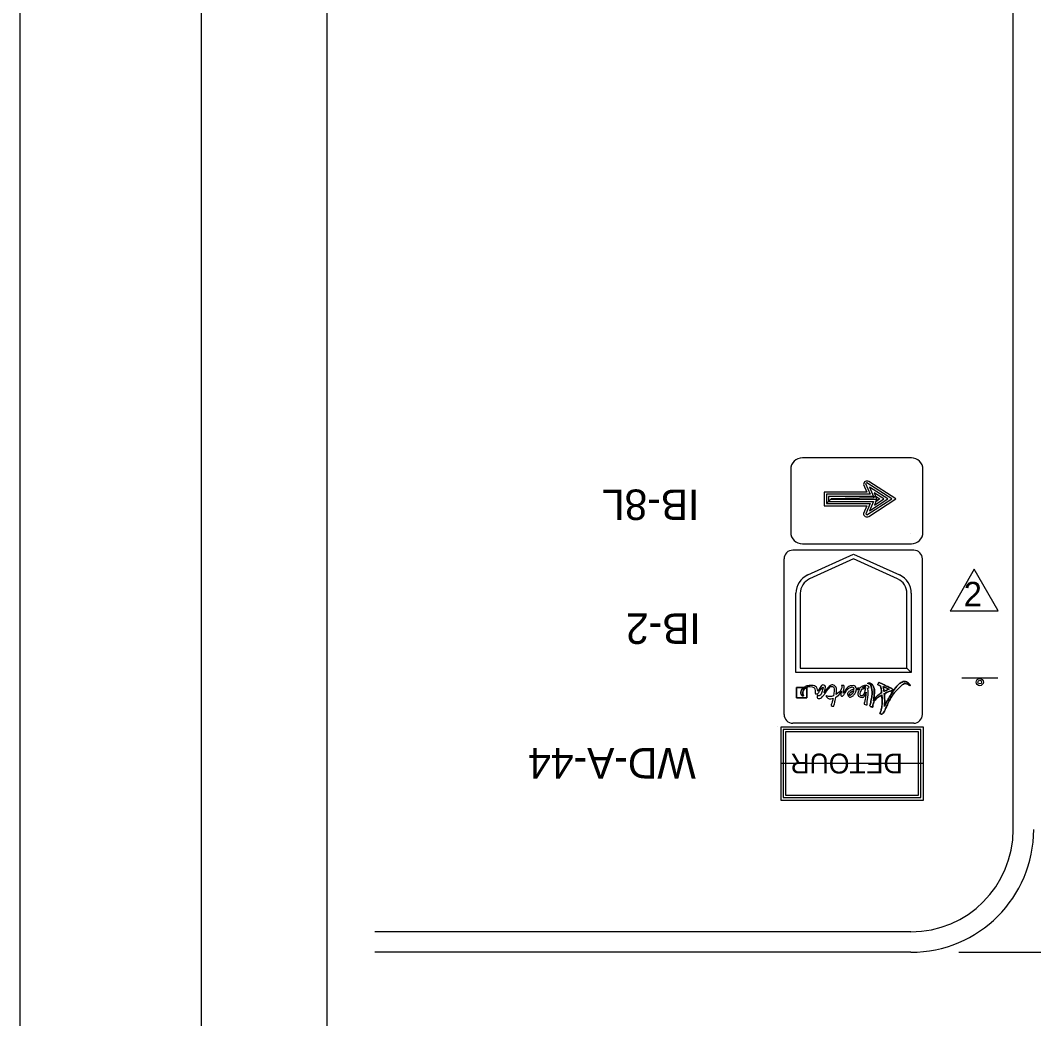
# Model space of a CAD drawing. Extents: x 1482 to 1692, y 225 to 494.
# Drawn here: x 1482.4 to 1542.3, y 383.2 to 442.2 of the extents above; entities that cross this region are included whole.
import ezdxf

# ---------------------------------------------------------------- set-up
doc = ezdxf.new("R2010")
doc.units = 0
for name, color, linetype in [('Level 17', 7, 'Continuous'), ('Level 2', 7, 'Continuous'), ('Level 53', 7, 'Continuous'), ('Level 60', 7, 'Continuous')]:
    doc.layers.add(name, color=color, linetype=linetype)

msp = doc.modelspace()

# ---------------------------------------------------------------- linework, layer by layer
at = {"layer": 'Level 17'}
for p, q in [((1535.059, 416.333), (1528.622, 416.333)), ((1527.938, 415.636), (1527.938, 411.938)), ((1535.737, 411.938), (1535.737, 415.636)), ((1532.238, 414.761), (1532.43, 414.3)), ((1534.152, 413.897), (1532.539, 414.928)), ((1532.43, 414.3), (1529.914, 414.3)), ((1529.914, 414.3), (1529.914, 413.501)), ((1532.539, 412.872), (1534.152, 413.897)), ((1529.914, 413.501), (1532.424, 413.501)), ((1532.43, 413.501), (1532.232, 413.039)), ((1535.002, 411.83), (1535.002, 411.83)), ((1528.622, 411.252), (1535.059, 411.252)), ((1540.173, 403.317), (1538.039, 403.317)), ((1527.164, 400.431), (1527.164, 400.431)), ((1527.164, 400.431), (1527.164, 400.431)), ((1527.164, 400.431), (1527.164, 400.431)), ((1527.164, 400.431), (1527.164, 400.431)), ((1535.773, 398.266), (1527.336, 398.266))]:
    msp.add_line(p, q, dxfattribs=at)
for points in [[(1529.814, 416.339), (1529.922, 416.339)], [(1530.049, 413.622), (1532.622, 413.622), (1532.366, 413.027), (1532.436, 412.962), (1533.914, 413.897), (1532.43, 414.845), (1532.359, 414.806), (1532.622, 414.173), (1530.043, 414.173), (1530.049, 413.622), (1530.17, 413.756), (1532.814, 413.756), (1532.59, 413.206), (1533.672, 413.897), (1532.59, 414.588), (1532.814, 414.038), (1530.17, 414.038), (1530.17, 413.756), (1530.306, 413.885), (1533.025, 413.885), (1532.878, 413.538), (1533.434, 413.897), (1532.864, 414.262), (1532.948, 414.058), (1533.204, 413.897), (1532.96, 413.736), (1533.012, 413.903), (1532.948, 414.058), (1532.82, 413.968), (1530.312, 413.903), (1530.306, 413.885)], [(1530.049, 413.622), (1532.622, 413.622)]]:
    msp.add_lwpolyline(points, dxfattribs=at)
for points in [[(1527.342, 396.112), (1535.768, 396.112), (1535.768, 400.42), (1527.342, 400.42)], [(1527.482, 396.254), (1535.628, 396.254), (1535.628, 400.28), (1527.482, 400.28)], [(1527.624, 396.394), (1535.486, 396.394), (1535.486, 400.14), (1527.624, 400.14)]]:
    msp.add_lwpolyline(points, close=True, dxfattribs=at)
for radius in [0.213, 0.107]:
    msp.add_circle((1539.102, 403.078), radius, dxfattribs=at)
for centre, radius, start, end in [((1528.623, 415.641), 0.692, 90, 180), ((1535.053, 415.641), 0.692, 0, 90), ((1532.435, 414.761), 0.199, 57.50145, 179.89494), ((1532.432, 413.038), 0.199, 179.89425, 302.49622), ((1528.623, 411.937), 0.692, 180, 270), ((1535.053, 411.937), 0.692, 270, 0)]:
    msp.add_arc(centre, radius, start, end, dxfattribs=at)
at = {"layer": 'Level 2'}
for p, q in [((1541.08, 394.372), (1541.08, 469.813)), ((1535.197, 410.874), (1528.055, 410.874)), ((1527.537, 401.169), (1527.537, 410.356)), ((1528.938, 409.409), (1531.647, 410.641)), ((1531.647, 410.36), (1529.044, 409.176)), ((1531.647, 410.641), (1534.356, 409.409)), ((1534.25, 409.176), (1531.647, 410.36)), ((1535.715, 401.169), (1535.715, 410.356)), ((1528.239, 403.655), (1528.239, 408.323)), ((1528.495, 408.323), (1528.495, 403.91)), ((1534.799, 403.91), (1534.799, 408.323)), ((1535.055, 408.323), (1535.055, 403.655)), ((1535.055, 403.655), (1528.239, 403.655)), ((1528.495, 403.91), (1534.799, 403.91)), ((1535.055, 403.655), (1534.799, 403.91)), ((1534.799, 403.91), (1535.055, 403.655)), ((1535.197, 400.651), (1528.055, 400.651)), ((1535.197, 400.651), (1528.055, 400.651)), ((1535.032, 388.323), (1503.354, 388.323)), ((1535.032, 387.114), (1503.354, 387.114)), ((1537.868, 387.114), (1555.432, 387.114))]:
    msp.add_line(p, q, dxfattribs=at)
for centre, radius, start, end in [((1528.055, 410.356), 0.518, 90, 180), ((1535.197, 410.356), 0.518, 360, 90), ((1529.432, 408.323), 1.193, 114.45682, 180), ((1529.432, 408.323), 0.937, 114.45682, 180), ((1533.862, 408.323), 0.937, 360, 65.54318), ((1533.862, 408.323), 1.193, 360, 65.54318), ((1528.055, 401.169), 0.518, 180, 270), ((1535.197, 401.169), 0.518, 270, 360), ((1535.032, 394.372), 6.048, 270, 359.99999), ((1535.032, 394.372), 7.258, 270, 359.99999)]:
    msp.add_arc(centre, radius, start, end, dxfattribs=at)
at = {"layer": 'Level 53'}
msp.add_line((1528.717, 402.766), (1528.867, 402.766), dxfattribs=at)
msp.add_lwpolyline([(1528.717, 402.766), (1528.276, 402.766), (1528.276, 402.158), (1528.885, 402.158), (1528.885, 402.766), (1528.867, 402.766)], dxfattribs=at)
for points, degree in [([(1532.53, 402.987), (1532.595, 402.977), (1532.681, 402.888), (1532.706, 402.742), (1532.753, 402.478), (1532.726, 402.218), (1532.648, 401.831), (1532.633, 401.757), (1532.583, 401.63), (1532.743, 401.606), (1532.793, 401.598), (1532.767, 401.623), (1532.781, 401.69), (1532.842, 401.979), (1533.078, 402.187), (1533.315, 402.326), (1533.34, 401.996), (1533.33, 401.629), (1533.268, 401.404), (1533.215, 401.214), (1533.153, 401.249), (1533.23, 401.209), (1533.312, 401.167), (1533.399, 401.223), (1533.47, 401.364), (1533.541, 401.505), (1533.867, 402.273), (1534.388, 402.791), (1534.655, 403.056), (1534.896, 402.92), (1534.944, 402.879), (1534.983, 402.846), (1534.998, 402.897), (1534.949, 402.949), (1534.733, 403.182), (1534.418, 403.049), (1534.304, 402.934), (1533.987, 402.617), (1533.618, 401.935), (1533.469, 401.645), (1533.483, 401.808), (1533.487, 402.082), (1533.457, 402.402), (1533.618, 402.481), (1533.763, 402.527), (1533.831, 402.545), (1533.905, 402.564), (1533.951, 402.594), (1533.952, 402.629), (1533.954, 402.666), (1533.904, 402.698), (1533.832, 402.732), (1533.705, 402.792), (1533.331, 402.969), (1533.239, 403.023), (1533.16, 403.068), (1533.121, 403.033), (1533.098, 402.983), (1533.067, 402.919), (1533.151, 402.882), (1533.232, 402.857), (1533.263, 402.749), (1533.288, 402.603), (1533.305, 402.442), (1533.115, 402.325), (1532.927, 402.169), (1532.82, 401.975), (1532.847, 402.137), (1532.916, 402.691), (1532.742, 402.925), (1532.703, 402.976), (1532.618, 403.033), (1532.535, 403.024), (1532.496, 403.021), (1532.476, 402.995), (1532.48, 402.987), (1532.484, 402.979), (1532.507, 402.99), (1532.53, 402.987)], 3), ([(1532.82, 401.975), (1532.847, 402.137), (1532.916, 402.691), (1532.742, 402.925), (1532.703, 402.976), (1532.618, 403.033), (1532.535, 403.024), (1532.496, 403.021), (1532.476, 402.995), (1532.48, 402.987), (1532.484, 402.979), (1532.507, 402.99), (1532.53, 402.987)], 3), ([(1533.457, 402.402), (1533.618, 402.481), (1533.763, 402.527), (1533.831, 402.545), (1533.905, 402.564), (1533.951, 402.594), (1533.952, 402.629), (1533.954, 402.666), (1533.904, 402.698), (1533.832, 402.732), (1533.705, 402.792), (1533.331, 402.969), (1533.239, 403.023), (1533.16, 403.068), (1533.121, 403.033), (1533.098, 402.983), (1533.067, 402.919), (1533.151, 402.882), (1533.232, 402.857)], 3), ([(1533.315, 402.326), (1533.34, 401.996), (1533.33, 401.629), (1533.268, 401.404), (1533.215, 401.214), (1533.153, 401.249), (1533.23, 401.209), (1533.312, 401.167), (1533.399, 401.223), (1533.47, 401.364), (1533.541, 401.505), (1533.867, 402.273), (1534.388, 402.791), (1534.655, 403.056), (1534.896, 402.92), (1534.944, 402.879), (1534.983, 402.846), (1534.998, 402.897), (1534.949, 402.949), (1534.733, 403.182), (1534.418, 403.049), (1534.304, 402.934), (1533.987, 402.617), (1533.618, 401.935), (1533.469, 401.645)], 3), ([(1528.885, 402.158), (1528.885, 402.158), (1528.885, 402.766), (1528.885, 402.766), (1528.885, 402.766), (1528.867, 402.766), (1528.867, 402.766), (1528.735, 402.687), (1528.646, 402.536), (1528.646, 402.412), (1528.647, 402.304), (1528.703, 402.31), (1528.697, 402.295), (1528.679, 402.252), (1528.544, 402.276), (1528.536, 402.428), (1528.53, 402.556), (1528.597, 402.681), (1528.717, 402.766), (1528.717, 402.766), (1528.276, 402.766), (1528.276, 402.766), (1528.276, 402.766), (1528.276, 402.158), (1528.276, 402.158), (1528.276, 402.158), (1528.885, 402.158), (1528.885, 402.158)], 3), ([(1528.867, 402.766), (1528.735, 402.687), (1528.646, 402.536), (1528.646, 402.412), (1528.647, 402.304), (1528.703, 402.31), (1528.697, 402.295), (1528.679, 402.252), (1528.544, 402.276), (1528.536, 402.428), (1528.53, 402.556), (1528.597, 402.681), (1528.717, 402.766)], 3), ([(1529.528, 402.535), (1529.513, 402.66), (1529.43, 402.876), (1529.093, 402.876), (1528.941, 402.876), (1528.812, 402.834), (1528.717, 402.766)], 3), ([(1528.867, 402.766), (1528.923, 402.799), (1528.987, 402.82), (1529.055, 402.82)], 2), ([(1529.055, 402.82), (1529.304, 402.82), (1529.369, 402.626), (1529.381, 402.53), (1529.389, 402.466), (1529.375, 402.374), (1529.485, 402.386), (1529.563, 402.395), (1529.632, 402.545), (1529.73, 402.672), (1529.814, 402.78), (1529.852, 402.77), (1529.832, 402.677), (1529.808, 402.56), (1529.71, 402.286), (1529.599, 402.266), (1529.547, 402.257), (1529.529, 402.347), (1529.505, 402.29), (1529.481, 402.234), (1529.503, 402.111), (1529.619, 402.111), (1529.699, 402.111), (1529.796, 402.197), (1529.876, 402.294), (1529.945, 402.379), (1530.296, 402.895), (1530.443, 402.784), (1530.511, 402.732), (1530.506, 402.52), (1530.462, 402.27)], 3), ([(1529.896, 402.462), (1529.974, 402.638), (1530.019, 402.863), (1529.901, 402.898), (1529.764, 402.938), (1529.655, 402.71), (1529.528, 402.535)], 3), ([(1530.614, 402.348), (1530.642, 402.583), (1530.632, 402.794), (1530.525, 402.861), (1530.328, 402.984), (1530.05, 402.66), (1529.896, 402.462)], 3), ([(1530.59, 402.184), (1530.72, 402.258), (1530.84, 402.382), (1530.928, 402.546)], 2), ([(1531.04, 402.426), (1531.054, 402.572), (1531.15, 402.892), (1530.987, 402.875), (1530.923, 402.869), (1530.951, 402.859), (1530.947, 402.804), (1530.933, 402.611), (1530.773, 402.448), (1530.614, 402.348)], 3), ([(1530.928, 402.546), (1530.913, 402.47), (1530.889, 402.387), (1530.887, 402.331), (1530.886, 402.271), (1530.926, 402.258), (1530.942, 402.254), (1530.976, 402.244), (1531.018, 402.261), (1531.059, 402.319), (1531.156, 402.455), (1531.277, 402.669), (1531.463, 402.759), (1531.595, 402.824), (1531.654, 402.759), (1531.657, 402.659)], 3), ([(1531.799, 402.693), (1531.785, 402.8), (1531.716, 402.882), (1531.553, 402.867), (1531.323, 402.846), (1531.118, 402.562), (1531.04, 402.426)], 3), ([(1531.657, 402.659), (1531.631, 402.651), (1531.607, 402.642), (1531.588, 402.634), (1531.347, 402.527), (1531.264, 402.366), (1531.325, 402.268), (1531.383, 402.175), (1531.549, 402.203), (1531.68, 402.341), (1531.745, 402.409), (1531.795, 402.526), (1531.8, 402.633)], 3), ([(1531.528, 402.354), (1531.448, 402.279), (1531.408, 402.284), (1531.397, 402.304), (1531.374, 402.348), (1531.469, 402.501), (1531.651, 402.585)], 3), ([(1531.651, 402.585), (1531.635, 402.503), (1531.592, 402.412), (1531.528, 402.354)], 2), ([(1532.041, 402.732), (1531.96, 402.721), (1531.876, 402.708), (1531.799, 402.693)], 2), ([(1531.8, 402.633), (1531.856, 402.645), (1531.92, 402.655), (1531.991, 402.665)], 2), ([(1531.991, 402.665), (1531.878, 402.482), (1531.888, 402.234), (1532.053, 402.192), (1532.245, 402.143), (1532.342, 402.33), (1532.383, 402.485)], 3), ([(1532.342, 402.7), (1532.316, 402.505), (1532.215, 402.234), (1532.088, 402.277), (1532.016, 402.303), (1532.054, 402.531), (1532.147, 402.683)], 3), ([(1532.487, 402.717), (1532.555, 402.739), (1532.583, 402.791), (1532.495, 402.845), (1532.434, 402.882), (1532.301, 402.895), (1532.166, 402.828), (1532.117, 402.805), (1532.075, 402.771), (1532.041, 402.732)], 3), ([(1532.147, 402.683), (1532.209, 402.689), (1532.274, 402.695), (1532.342, 402.7)], 2), ([(1532.196, 402.749), (1532.23, 402.786), (1532.267, 402.811), (1532.308, 402.818)], 2), ([(1532.348, 402.761), (1532.314, 402.759), (1532.26, 402.755), (1532.196, 402.749)], 2), ([(1532.383, 402.485), (1532.371, 402.33), (1532.346, 402.141), (1532.311, 401.966), (1532.296, 401.892), (1532.246, 401.765), (1532.405, 401.741), (1532.456, 401.733), (1532.448, 401.757), (1532.444, 401.825), (1532.438, 401.917), (1532.54, 402.473), (1532.487, 402.717)], 3), ([(1532.308, 402.818), (1532.33, 402.821), (1532.348, 402.821), (1532.363, 402.818)], 2), ([(1532.363, 402.818), (1532.354, 402.81), (1532.349, 402.8), (1532.349, 402.787), (1532.349, 402.778), (1532.348, 402.77), (1532.348, 402.761)], 3), ([(1532.53, 402.987), (1532.595, 402.977), (1532.681, 402.888), (1532.706, 402.742), (1532.753, 402.478), (1532.726, 402.218), (1532.648, 401.831), (1532.633, 401.757), (1532.583, 401.63), (1532.743, 401.606), (1532.793, 401.598), (1532.767, 401.623), (1532.781, 401.69), (1532.842, 401.979), (1533.078, 402.187), (1533.315, 402.326)], 3), ([(1533.305, 402.442), (1533.115, 402.325), (1532.927, 402.169), (1532.82, 401.975)], 2), ([(1533.232, 402.857), (1533.263, 402.749), (1533.288, 402.603), (1533.305, 402.442)], 2), ([(1533.444, 402.521), (1533.429, 402.65), (1533.413, 402.744), (1533.394, 402.813)], 2), ([(1533.394, 402.813), (1533.477, 402.783), (1533.595, 402.735), (1533.749, 402.656)], 2), ([(1533.749, 402.656), (1533.664, 402.626), (1533.557, 402.581), (1533.444, 402.521), (1533.429, 402.65), (1533.413, 402.744), (1533.394, 402.813), (1533.477, 402.783), (1533.595, 402.735), (1533.749, 402.656)], 3), ([(1533.749, 402.656), (1533.664, 402.626), (1533.557, 402.581), (1533.444, 402.521)], 2), ([(1533.469, 401.645), (1533.483, 401.808), (1533.487, 402.082), (1533.457, 402.402)], 2), ([(1530.462, 402.27), (1530.288, 402.203), (1530.143, 402.225), (1530.061, 402.264), (1530.021, 402.284), (1530.015, 402.281), (1530.032, 402.236), (1530.058, 402.171), (1530.198, 402.068), (1530.417, 402.115), (1530.422, 402.117), (1530.428, 402.118), (1530.433, 402.119)], 3), ([(1530.433, 402.119), (1530.415, 402.038), (1530.395, 401.956), (1530.372, 401.876), (1530.352, 401.802), (1530.292, 401.675), (1530.449, 401.651), (1530.499, 401.643), (1530.477, 401.667), (1530.494, 401.735), (1530.524, 401.86), (1530.563, 402.021), (1530.59, 402.184)], 3)]:
    msp.add_open_spline(points, degree=degree, dxfattribs=at)
at = {"layer": 'Level 60'}
for points in [[(1482.41, 493.623), (1692.41, 493.623), (1692.41, 224.631), (1482.41, 224.631)], [(1493.127, 487.958), (1687.519, 487.958), (1687.519, 230.208), (1493.127, 230.208)], [(1500.536, 487.818), (1687.41, 487.818), (1687.41, 230.436), (1500.536, 230.436)]]:
    msp.add_lwpolyline(points, close=True, dxfattribs=at)
for points in [[(1538.777, 409.753), (1537.384, 407.328)], [(1540.171, 407.328), (1538.777, 409.753)], [(1537.384, 407.328), (1537.358, 407.283), (1540.197, 407.283), (1540.171, 407.328)]]:
    msp.add_lwpolyline(points, dxfattribs=at)

# ---------------------------------------------------------------- texts
at = {"layer": 'Level 17'}
for s, height, p in [('IB-8L', 1.8, (1522.53, 414.457)), ('IB-2', 1.8, (1522.613, 407.135)), ('WD-A-44', 1.8, (1522.323, 399.182)), ('DETOUR', 1.1758, (1534.548, 398.854))]:
    msp.add_text(s, height=height, rotation=180, dxfattribs=at).set_placement(p)
at = {"layer": 'Level 60'}
msp.add_text('2', height=1.448, rotation=360, dxfattribs=at).set_placement((1538.15, 407.552))

doc.saveas('drawing.dxf')
